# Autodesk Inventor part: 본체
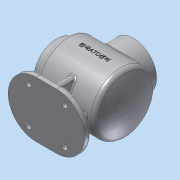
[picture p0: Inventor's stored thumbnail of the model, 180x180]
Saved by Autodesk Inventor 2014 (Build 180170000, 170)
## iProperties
Created: 2023-01
Part Number: 본체
Material: 알루미늄 6061
Document SubType Name: Modeling
Designer: dg
Density: 2.71 g/cm^3
Appearance: 알루미늄 - 평지
Mass: 1038.22 g
Surface Area: 1157.5 cm^2
Volume: 383.109 cm^3
Author: dg
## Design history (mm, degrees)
sketch "스케치1"
  geometry: L1 (0, 0)-(0, 38); L2 (0, 38)-(12, 38); L3 (12, 38)-(12, 50); L4 (12, 50)-(111.087, 50); L5 (0, 0)-(122, 0); L6 (0, 27)-(17, 27); L7 (17, 27)-(17, 45); L8 (17, 45)-(107.83, 45); A1 r 120 centre (2, 0) between (122, 0) and (111.087, 50); A2 r 115 centre (2, 0) between (117, 0) and (107.83, 45)
  constraints: 17 end point, 4 point on circle, 3 parallel, 3 perpendicular, 2 centre point, 2 point on line, 1 concentric, 1 horizontal, 1 vertical
  dimensions: "d1" = 54 diameter of L6 L5; "d2" = 76 diameter of L2 L5; "d3" = 100 diameter of L4 L5; "d4" = 17 distance of L6.start L6.end; "d6" = 5 radial gap between concentric circles of A1 A2; "d7" = 90 diameter of L8 L5; "d8" = 120 radius of A1; "d9" = 122 distance from line of L5.end L1; "d10" = 5 distance between parallel lines of L3 L7; "d11" = 117 distance from line of L1 A2.start
revolve "회전1" sketch "스케치1" stored, may be unused: angle "d12" = 90 deg
node "작업 평면1"
sketch "스케치2"
  geometry: L1 (-80, 0)-(-46, 0); L2 (-80, -46)-(-46, -46); L3 (-46, 46)-(-80, 46); L4 (-58, 35)-(-68, 35); L5 (-68, 35)-(-68, -35); L6 (-68, -35)-(-58, -35); L7 (-58, -35)-(-58, 35); L8 (0, 38)-(0, -38) reference; A1 r 46 centre (-80, 0) between (-80, 46) and (-80, -46); A2 r 46 centre (-46, 0) between (-46, -46) and (-46, 46); 8 further points
  constraints: 16 end point, 6 midpoint, 6 point on circle, 4 tangent, 3 parallel, 2 centre point, 2 horizontal, 1 coincident, 1 horizontal alignment, 1 perpendicular, 1 vertical alignment
  dimensions: "d14" = 10 distance of L4.start L4.end; "d15" = 70 distance of L4.end L5.end; "d16" = 92 distance between parallel lines of L2 L3; "d17" = 126 distance of point (0, 0) point (-126, 0)
extrude "돌출1" join sketch "스케치2" distance "d21" = 10; taper "d22" = 0 deg
extrude "돌출2" join sketch "스케치2" stored distance "d23" = 10; taper "d24" = 0 deg
sketch "스케치3"
  geometry: L1 (111.087, -50)-(111.087, 50) reference; L2 (12, -50)-(12, 50) reference; L3 (58, -35.707)-(58, -35.707) reference; L4 (58, -35.707)-(68, -35.707) reference; L5 (68, -35.707)-(68, -35.707) reference; L6 (68, -35.707)-(58, -35.707) reference; L7 (12, -50)-(111.087, -50) reference; L8 (46, -70)-(0, -70) reference; L9 (80, -70)-(46, -70) reference; L10 (126, -70)-(80, -70) reference; L11 (12, -50)-(111.087, -50) reference; L12 (28.359, -50)-(23, -70); L13 (97.641, -50)-(103, -70); L14 (28.359, -50)-(97.641, -50); 3 further points
  constraints: 6 end point, 4 midpoint, 2 point on line, 1 collinear, 1 vertical alignment
  dimensions: "d25" = 105 deg angle of L8 L12; "d26" = 105 deg angle of L10 L13; "d27" = 80 distance of L13.end L12.end
  node "투영된 루프1"
feature "리브1" dims "d28" = 1, "d29" = 10, "d30" = 0, "d31" = 0, "d32" = 1, "d33" = 1
feature "리브2" dims "d34" = 1, "d35" = 10, "d36" = 0, "d37" = 0, "d38" = 1, "d39" = 1
node "작업 평면2"
sketch "스케치4"
  geometry: L1 (-80, -46)-(-46, -46) reference; C1 r 38 at (-63, 0); C2 r 27 at (-63, 0); 2 further points
  constraints: 2 centre point, 1 coincident, 1 horizontal alignment, 1 midpoint, 1 vertical alignment
  dimensions: "d41" = 54 diameter of C2; "d42" = 76 diameter of C1
extrude "돌출3" join sketch "스케치4" stored distance "d43" = 10; taper "d44" = 0 deg
extrude "돌출4" cut sketch "스케치4" stored distance "d45" = 10; taper "d46" = 0 deg
sketch "스케치5"
  geometry: C1 r 38 at (0, 0) reference; 1 further point
  constraints: 1 vertical alignment
  dimensions: "d47" = 32.5 distance of C1.centre point (0, 32.5)
hole "구멍1" sketch "스케치5" at (0, 32.5) diameter "d48" = 3.242; stored, may be unused: countersink angle "d52" = 90 deg, drill point angle "d54" = 118 deg; dims "d49" = 8, "d50" = 4, "d51" = 2, "d53" = 10
sketch "스케치6"
  geometry: C1 r 27 at (0, 0) reference; 2 further points
  constraints: 1 vertical alignment
  dimensions: "d58" = 32.5 distance of C1.centre point (0, 32.5)
sketch "스케치7"
  geometry: L1 (58, 35)-(68, 35) reference; C1 r 4.5 at (33, 30); A1 r 46 centre (46, 0) between (46, 46) and (46, -46) reference; 2 further points
  constraints: 1 centre point, 1 midpoint
  dimensions: "d59" = 9 diameter of C1; "d60" = 30 horizontal distance of C1.centre point (63, 35); "d61" = 30 vertical distance of A1.centre C1.centre
extrude "돌출5" cut sketch "스케치7" stored distance "d62" = 10; taper "d63" = 0 deg
fillet "모깎기1" dims "d67" = 3
fillet "모깎기3" dims "d69" = 8
chamfer "모따기1" distance "d70" = 1; stored, may be unused: second distance "d71" = 2, angle "d72" = 45 deg
hole "구멍2" sketch "스케치6" diameter "d73" = 3.242; stored, may be unused: countersink angle "d77" = 90 deg, drill point angle "d79" = 118 deg; dims "d74" = 8, "d75" = 4, "d76" = 2, "d78" = 10
fillet "모깎기4" dims "d83" = 3
node "작업 평면3"
sketch "스케치9"
  geometry: L1 (-15.544, -80)-(18.456, -80) reference; L2 (-61.544, -38)-(-61.544, 38) reference; 2 further points
  constraints: 1 other
  dimensions: "d84" = 80 distance from line of L1 point (1.456, 0); "d85" = 63 distance from line of point (1.456, 0) L2
feature "엠보싱1" sketch "스케치9" dims "d1" = 54, "d2" = 76, "d3" = 100, "d4" = 17, "d6" = 5, "d7" = 90, "d8" = 120, "d9" = 122, "d10" = 5, "d11" = 117, "d86" = 0.5, "d87" = 0
node "솔리드1"
pattern_circular "원형 패턴1" dims angle "d56" = 360 deg
pattern_circular "원형 패턴2" dims angle "d65" = 360 deg
pattern_circular "원형 패턴3" dims angle "d81" = 360 deg
other parameters: "d40" = 64
